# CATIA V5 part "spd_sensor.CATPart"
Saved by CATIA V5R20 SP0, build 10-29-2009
Part number: sensorst
Bounding box of the stored display mesh (mm): x 0 to 18.5, y 0 to 24.4, z 0 to 7.1
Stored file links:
  C:\Users\user\OneDrive\바탕 화면\지혜 카티아\fixer.CATPart
  C:\Users\user\OneDrive\바탕 화면\지혜 카티아\fix2.CATPart
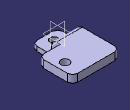
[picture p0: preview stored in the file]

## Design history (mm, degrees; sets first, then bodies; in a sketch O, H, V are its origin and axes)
Body1 (main body)
  Sketch1 on yz-plane, origin (0, 0, 0), H (0, 1, 0), V (0, 0, 1)
    construction line L1 through (0, 0) direction (1, 0)
    line L2 (0, 0) -> (11.2, 0)
    line L3 (0, 0) -> (0, 1.8)
    line L4 (0, 1.8) -> (7.76, 1.8)
    line L5 (7.76, 1.8) -> (7.76, 7.1)
    line L6 (7.76, 7.1) -> (24.4, 7.1)
    line L7 (24.4, 7.1) -> (24.4, 4.1)
    line L8 (24.4, 4.1) -> (11.2, 4.1)
    line L9 (11.2, 4.1) -> (11.2, 0)
    length L2 = 11.2
    length L4 = 7.76
    length L5 = 5.3
    length L6 = 16.64
    horizontal: L2 L1, L4 L1, L6 L1, L8 L1
    vertical: L3 V, L5 V, L7 V, L9 V
  Pad1: profile Sketch1, direction (1, 0, 0), length 10
  Sketch2 on end face of Pad1, origin (10, 0, 0), H (0, 1, 0), V (0, 0, 1)
    line L1 (11.2, 7.1) -> (24.4, 7.1)
    line L2 (24.4, 4.1) -> (11.2, 4.1)
    line L3 (24.4, 7.1) -> (24.4, 4.1)
    line L4 (11.2, 4.1) -> (11.2, 7.1)
    horizontal: L1 H, L2 H
    vertical: L3 V, L4 V
  Pad2: profile Sketch2, direction (1, 0, 0), length 8.5
  Sketch3 on face of Pad1 from Sketch1.L4, origin (4.6124, 4.1808, 1.8), H (1, 0, 0), V (0, 1, 0)
    point P1 (-0.0124, -0.8808)
    point P2 (0, 0)
    construction line L1 through (0, 0) direction (1, 0)
    construction line L2 through (0, 0) direction (0, 1)
    point P3 (-0.301, 2.6831)
    point P4 (0, 0)
    construction line L3 through (0, 0) direction (1, 0)
    construction line L4 through (0, 0) direction (0, 1)
    reference projected line E1 (-4.6124, -4.1808) -> (5.3876, -4.1808) from edge [face of Pad1 from Sketch1.L3 | face of Pad1 from Sketch1.L4]
    reference projected line E2 (5.3876, 3.5792) -> (5.3876, -4.1808) from edge [face of Pad1 from Sketch1.L4 | end face of Pad1]
    distance P1 E1 = 3.3
    distance P1 E2 = 5.4
  Hole1: placed by Sketch3, at (4.6, 3.3, 1.8) direction (0, 0, -1), diameter 3.35, depth 10
  Sketch4 on face of Pad2, origin (14.4616, 17.1826, 7.1), H (1, 0, 0), V (0, 1, 0)
    point P1 (0.7384, 1.0174)
    reference projected line E1 (-4.4616, 7.2174) -> (-4.4616, -9.4226) from edge [face of Pad2 | end face of Pad1]
    reference projected line E2 (-4.4616, -5.9826) -> (4.0384, -5.9826) from edge [face of Pad2 from Sketch2.L4 | face of Pad2]
    distance P1 E1 = 5.2
    distance P1 E2 = 7
  Hole2: placed by Sketch4, at (15.2, 18.2, 7.1) direction (0, 0, -1), diameter 3.44, depth 10
  Fillet1: radius 2, on edge [face of Pad2 | end face of Pad2]; edge [start face of Pad1 | face of Pad2]; edge [face of Pad1 from Sketch1.L3 | end face of Pad1]; edge [start face of Pad1 | face of Pad1 from Sketch1.L3]
  Fillet2: radius 2, on edge [face of Pad1 from Sketch1.L5 | face of Pad2]
  Fillet3: radius 2, on edge [face of Pad2 from Sketch2.L4 | end face of Pad2]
